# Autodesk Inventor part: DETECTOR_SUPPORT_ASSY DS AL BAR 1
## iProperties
Shininess: 64.0
Length Units: 11272
Angle Units: 11279
Time Units: 11290
Mass Units: 11286
Length Display Precision: 3
Angle Display Precision: 2
Compacted: True
Part Number: DETECTOR_SUPPORT_ASSY DS AL BAR 1
Document SubType Name: Modeling
Created: 2004-08
Designer: John Blackburn
Material: ALUMINUM
Manufacturer: Standard
Standards Organization: Custom
Density: 0.0
Volumn: 0.0
Area: 0.0
PropertySet Name: Model Information
Control State: 0
Master: False
Checked Out: False
Author: John Blackburn
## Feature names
1. ExtrusionMidplane1
2. AM_HOLE_SI0029_1 [Hole]
3. Rectangular Pattern1
4. Hole1
5. Rectangular Pattern2
